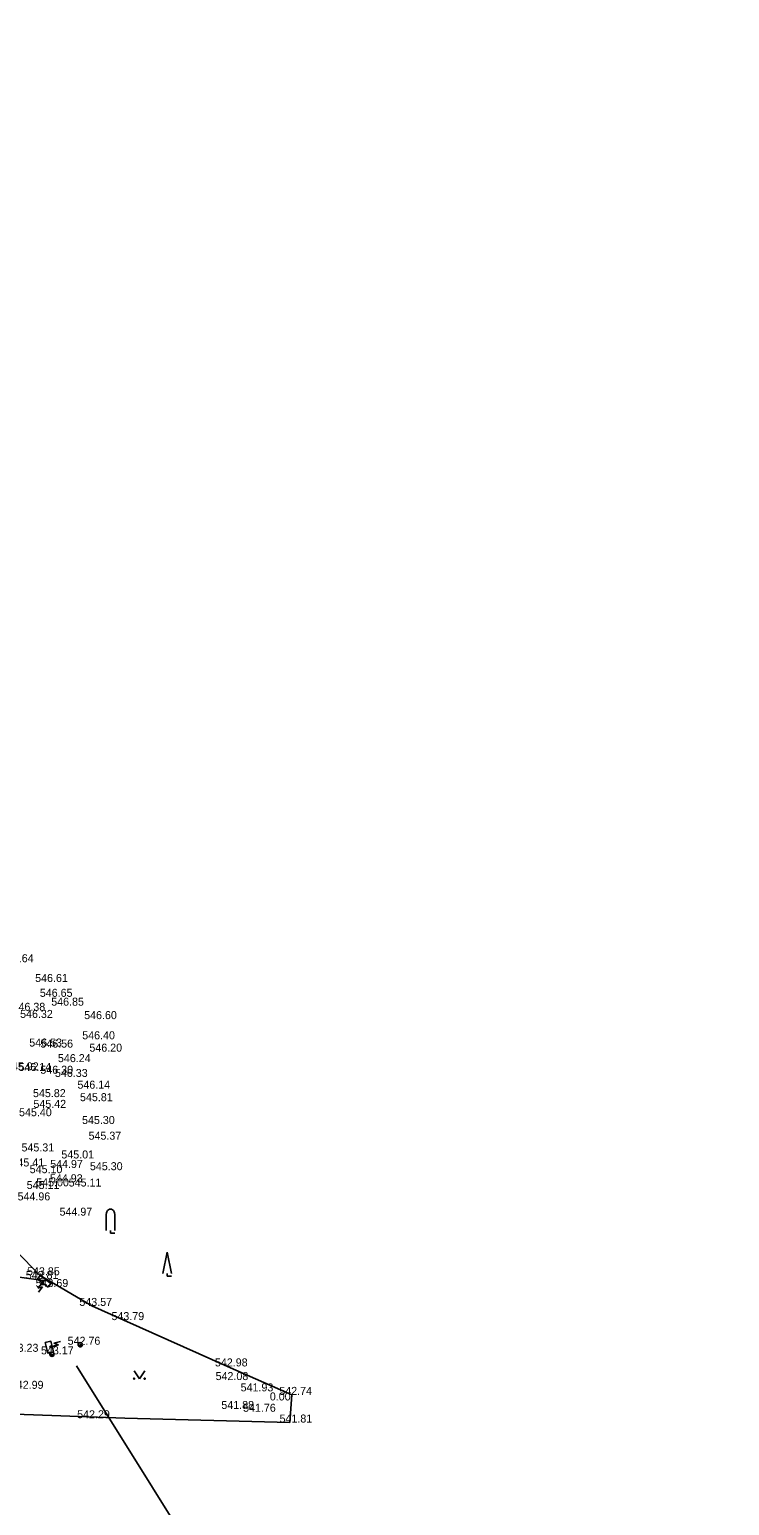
# Model space of a CAD drawing. Extents: x -669393 to -668650, y -1126925 to -1126294.
# Drawn here: x -668849.7 to -668784, y -1126670.3 to -1126531.9 of the extents above; entities that cross this region are included whole.
import ezdxf

# ---------------------------------------------------------------- set-up
doc = ezdxf.new("R2010")
doc.units = 0
for name, color, linetype in [('G_Bod_tecka', 7, 'Continuous'), ('G_Bod_vyska', 7, 'Continuous'), ('G_Ploty', 7, 'Continuous'), ('G_Ploty_vstupy', 7, 'Continuous'), ('G_Site-Rozvadece', 7, 'Continuous'), ('G_Site-Sloupy', 7, 'Continuous'), ('G_Z_ELsilove_nadz_kotovane', 7, 'Continuous'), ('G_Z_ELsilove_podz_kotovane', 7, 'Continuous'), ('G_Zelen-Znacky', 7, 'Continuous'), ('Vrstva 4', 7, 'Continuous')]:
    doc.layers.add(name, color=color, linetype=linetype)

msp = doc.modelspace()

# ---------------------------------------------------------------- linework, layer by layer
at = {"layer": 'G_Bod_tecka'}
for p, q in [((-668848.03, -1126621.19), (-668848.03, -1126621.19)), ((-668847.53, -1126622.58), (-668847.53, -1126622.58)), ((-668846.47, -1126623.41), (-668846.47, -1126623.41)), ((-668849.39, -1126624.56), (-668849.39, -1126624.56)), ((-668843.35, -1126624.67), (-668843.35, -1126624.67)), ((-668843.54, -1126626.56), (-668843.54, -1126626.56)), ((-668848.53, -1126627.24), (-668848.53, -1126627.24)), ((-668847.48, -1126627.34), (-668847.48, -1126627.34)), ((-668842.87, -1126627.72), (-668842.87, -1126627.72)), ((-668849.68, -1126629.53), (-668849.68, -1126629.53)), ((-668845.84, -1126628.7), (-668845.84, -1126628.7)), ((-668847.47, -1126629.79), (-668847.47, -1126629.79)), ((-668846.12, -1126630.09), (-668846.12, -1126630.09)), ((-668848.2, -1126631.98), (-668848.2, -1126631.98)), ((-668844.15, -1126631.19), (-668844.15, -1126631.19)), ((-668848.16, -1126632.99), (-668848.16, -1126632.99)), ((-668843.85, -1126632.36), (-668843.85, -1126632.36)), ((-668849.48, -1126633.77), (-668849.48, -1126633.77)), ((-668843.57, -1126634.5), (-668843.57, -1126634.5)), ((-668842.99, -1126635.97), (-668842.99, -1126635.97)), ((-668849.34, -1126637.07), (-668849.34, -1126637.07)), ((-668845.58, -1126637.73), (-668845.58, -1126637.73)), ((-668848.63, -1126639.11), (-668848.63, -1126639.11)), ((-668846.58, -1126638.62), (-668846.58, -1126638.62)), ((-668842.83, -1126638.83), (-668842.83, -1126638.83)), ((-668848.99, -1126640.59), (-668848.99, -1126640.59)), ((-668847.85, -1126640.34), (-668847.85, -1126640.34)), ((-668846.6, -1126639.96), (-668846.6, -1126639.96)), ((-668845.05, -1126640.36), (-668845.05, -1126640.36)), ((-668849.63, -1126641.66), (-668849.63, -1126641.66)), ((-668845.7, -1126643.09), (-668845.7, -1126643.09)), ((-668848.76, -1126648.68), (-668848.76, -1126648.68)), ((-668848.94, -1126649.03), (-668848.94, -1126649.03)), ((-668847.94, -1126649.78), (-668847.94, -1126649.78)), ((-668843.85, -1126651.55), (-668843.85, -1126651.55)), ((-668840.83, -1126652.88), (-668840.83, -1126652.88)), ((-668844.93, -1126655.19), (-668844.93, -1126655.19)), ((-668847.59, -1126656.09), (-668847.59, -1126656.09)), ((-668831.12, -1126657.22), (-668831.12, -1126657.22)), ((-668831.04, -1126658.5), (-668831.04, -1126658.5)), ((-668828.86, -1126659.56), (-668828.86, -1126659.56)), ((-668825.09, -1126659.89), (-668825.09, -1126659.89)), ((-668830.67, -1126661.21), (-668830.67, -1126661.21)), ((-668826.36, -1126660.41), (-668826.36, -1126660.41)), ((-668844.05, -1126662.08), (-668844.05, -1126662.08)), ((-668828.61, -1126661.47), (-668828.61, -1126661.47)), ((-668825.27, -1126662.48), (-668825.27, -1126662.48))]:
    msp.add_line(p, q, dxfattribs=at)
at = {"layer": 'G_Ploty'}
for p, q in [((-668849.45, -1126647.96), (-668855.46, -1126641.72)), ((-668843.85, -1126651.55), (-668840.83, -1126652.88)), ((-668831.12, -1126657.22), (-668840.83, -1126652.88)), ((-668825.09, -1126659.89), (-668831.12, -1126657.22)), ((-668825.27, -1126662.48), (-668825.09, -1126659.89)), ((-668840.75, -1126662.06), (-668856.29, -1126661.51)), ((-668825.27, -1126662.48), (-668840.75, -1126662.06))]:
    msp.add_line(p, q, dxfattribs=at)
msp.add_lwpolyline([(-668843.85, -1126651.55), (-668848.7, -1126648.71), (-668848.76, -1126648.68)], dxfattribs=at)
at = {"layer": 'G_Ploty_vstupy'}
msp.add_line((-668848.76, -1126648.68), (-668849.45, -1126647.96), dxfattribs=at)
at = {"layer": 'G_Site-Rozvadece'}
for p, q in [((-668848.94, -1126649.03), (-668848.7, -1126648.71)), ((-668848.7, -1126648.71), (-668847.7, -1126649.46)), ((-668848.94, -1126649.03), (-668847.94, -1126649.78)), ((-668848.9, -1126649.9), (-668848.35, -1126649.22)), ((-668848.47, -1126649.77), (-668848.9, -1126649.9)), ((-668848.86, -1126650.25), (-668848.47, -1126649.77)), ((-668848.35, -1126649.22), (-668848.59, -1126649.34)), ((-668848.42, -1126649.48), (-668848.35, -1126649.22)), ((-668847.7, -1126649.46), (-668847.94, -1126649.78)), ((-668846.97, -1126655.2), (-668847.82, -1126655.42)), ((-668847.61, -1126655.25), (-668847.82, -1126655.42)), ((-668847.82, -1126655.42), (-668847.56, -1126655.47)), ((-668846.79, -1126654.9), (-668847.4, -1126655.05)), ((-668847.4, -1126655.05), (-668846.97, -1126655.2))]:
    msp.add_line(p, q, dxfattribs=at)
msp.add_lwpolyline([(-668848.21, -1126654.99), (-668847.96, -1126655.98), (-668847.43, -1126655.84), (-668847.68, -1126654.86)], close=True, dxfattribs=at)
at = {"layer": 'G_Site-Sloupy'}
for centre in [(-668844.93, -1126655.19), (-668847.59, -1126656.09)]:
    msp.add_circle(centre, 0.2, dxfattribs=at)
for centre, radius in [((-668844.93, -1126655.19), 0.18), ((-668844.93, -1126655.19), 0.16), ((-668844.93, -1126655.19), 0.14), ((-668844.93, -1126655.19), 0.12), ((-668844.93, -1126655.19), 0.1), ((-668844.93, -1126655.19), 0.08), ((-668844.93, -1126655.19), 0.06), ((-668844.93, -1126655.19), 0.04), ((-668844.93, -1126655.19), 0.02), ((-668847.59, -1126656.09), 0.18), ((-668847.59, -1126656.09), 0.16), ((-668847.59, -1126656.09), 0.14), ((-668847.59, -1126656.09), 0.12), ((-668847.59, -1126656.09), 0.1), ((-668847.59, -1126656.09), 0.08), ((-668847.59, -1126656.09), 0.06), ((-668847.59, -1126656.09), 0.04), ((-668847.59, -1126656.09), 0.02)]:
    msp.add_arc(centre, radius, 180, 0, dxfattribs=at)
at = {"layer": 'G_Z_ELsilove_nadz_kotovane'}
msp.add_lwpolyline([(-668784.01, -1126754.51), (-668809.93, -1126713.68), (-668845.29, -1126657.16)], dxfattribs=at)
at = {"layer": 'G_Z_ELsilove_podz_kotovane'}
msp.add_lwpolyline([(-668862.99, -1126507.05), (-668868.36, -1126534.57), (-668870.31, -1126540.36), (-668871.27, -1126544.92), (-668872.24, -1126549.47), (-668872.88, -1126555.9), (-668873.53, -1126562.33), (-668872.56, -1126565.38), (-668872.66, -1126574.45), (-668872.93, -1126584.84), (-668873.2, -1126595.23), (-668868.61, -1126610.5), (-668866.81, -1126618.14), (-668864.25, -1126627.97), (-668861.68, -1126637.8), (-668858.49, -1126641.92), (-668855.29, -1126646.04), (-668854.01, -1126647.3), (-668852.73, -1126648.57), (-668848.15, -1126649.21)], dxfattribs=at)
msp.add_lwpolyline([(-668862.99, -1126507.05), (-668868.36, -1126534.57), (-668870.31, -1126540.36), (-668871.27, -1126544.92), (-668872.24, -1126549.47), (-668872.88, -1126555.9), (-668873.53, -1126562.33), (-668872.56, -1126565.38), (-668872.66, -1126574.45), (-668872.93, -1126584.84), (-668873.2, -1126595.23), (-668868.61, -1126610.5), (-668866.81, -1126618.14), (-668864.25, -1126627.97), (-668861.68, -1126637.8), (-668858.49, -1126641.92), (-668855.29, -1126646.04), (-668854.01, -1126647.3), (-668852.73, -1126648.57), (-668848.15, -1126649.21)], dxfattribs=at)
at = {"layer": 'G_Zelen-Znacky'}
for p, q in [((-668842.49, -1126644.47), (-668842.49, -1126642.97)), ((-668841.69, -1126642.97), (-668841.69, -1126644.47)), ((-668842.09, -1126644.47), (-668842.09, -1126644.72)), ((-668842.09, -1126644.72), (-668841.69, -1126644.72)), ((-668837.17, -1126648.5), (-668836.77, -1126646.5)), ((-668836.77, -1126646.5), (-668836.37, -1126648.5)), ((-668836.77, -1126648.5), (-668836.77, -1126648.75)), ((-668836.77, -1126648.75), (-668836.37, -1126648.75)), ((-668839.88, -1126657.62), (-668839.38, -1126658.37)), ((-668839.38, -1126658.37), (-668838.88, -1126657.62))]:
    msp.add_line(p, q, dxfattribs=at)
for centre in [(-668839.88, -1126658.37), (-668838.88, -1126658.37)]:
    msp.add_circle(centre, 0.05, dxfattribs=at)
msp.add_ellipse((-668842.09, -1126642.97), major_axis=(0, 0.5), ratio=0.8, start_param=4.712389, end_param=7.853982, dxfattribs=at)
at = {"layer": 'Vrstva 4'}
msp.add_lwpolyline([(-668862.99, -1126507.05), (-668868.36, -1126534.57), (-668870.31, -1126540.36), (-668871.27, -1126544.92), (-668872.24, -1126549.47), (-668872.88, -1126555.9), (-668873.53, -1126562.33), (-668872.56, -1126565.38), (-668872.66, -1126574.45), (-668872.93, -1126584.84), (-668873.2, -1126595.23), (-668868.61, -1126610.5), (-668866.81, -1126618.14), (-668864.25, -1126627.97), (-668861.68, -1126637.8), (-668858.49, -1126641.92), (-668855.29, -1126646.04), (-668854.01, -1126647.3), (-668852.73, -1126648.57), (-668848.15, -1126649.21)], dxfattribs=at)

# ---------------------------------------------------------------- texts
at = {"layer": 'G_Bod_vyska'}
for s, p in [('546.64', (-668852.37, -1126619.34)), ('546.61', (-668849.16, -1126621.19)), ('546.65', (-668848.72, -1126622.58)), ('546.85', (-668847.65, -1126623.41)), ('546.38', (-668851.28, -1126623.89)), ('546.32', (-668850.57, -1126624.56)), ('546.60', (-668844.56, -1126624.67)), ('546.53', (-668849.71, -1126627.24)), ('546.56', (-668848.67, -1126627.34)), ('546.40', (-668844.74, -1126626.56)), ('546.24', (-668847.02, -1126628.7)), ('546.20', (-668844.07, -1126627.72)), ('545.92', (-668851.9, -1126629.47)), ('546.14', (-668850.72, -1126629.53)), ('546.30', (-668848.67, -1126629.79)), ('546.33', (-668847.3, -1126630.09)), ('546.14', (-668845.19, -1126631.19)), ('545.82', (-668849.36, -1126631.98)), ('545.42', (-668849.32, -1126632.99)), ('545.81', (-668844.95, -1126632.36)), ('545.40', (-668850.67, -1126633.77)), ('545.30', (-668844.76, -1126634.5)), ('545.31', (-668850.44, -1126637.07)), ('545.37', (-668844.15, -1126635.97)), ('545.41', (-668851.38, -1126638.48)), ('544.97', (-668847.75, -1126638.62)), ('545.01', (-668846.7, -1126637.73)), ('545.10', (-668849.67, -1126639.11)), ('544.93', (-668847.77, -1126639.96)), ('545.30', (-668844.02, -1126638.83)), ('545.11', (-668849.95, -1126640.59)), ('545.00', (-668849.06, -1126640.34)), ('545.11', (-668846.01, -1126640.36)), ('544.96', (-668850.81, -1126641.66)), ('544.97', (-668846.87, -1126643.09)), ('543.81', (-668850.04, -1126649.03)), ('543.85', (-668849.92, -1126648.68)), ('543.69', (-668849.12, -1126649.78)), ('543.57', (-668845.01, -1126651.55)), ('543.79', (-668842, -1126652.88)), ('542.76', (-668846.11, -1126655.19)), ('543.23', (-668851.92, -1126655.85)), ('543.17', (-668848.61, -1126656.09)), ('542.98', (-668832.29, -1126657.22)), ('542.99', (-668851.44, -1126659.32)), ('542.08', (-668832.23, -1126658.5)), ('541.93', (-668829.88, -1126659.56)), ('0.00', (-668827.14, -1126660.41)), ('542.74', (-668826.25, -1126659.89)), ('542.29', (-668845.22, -1126662.08)), ('541.88', (-668831.69, -1126661.21)), ('541.76', (-668829.65, -1126661.47)), ('541.81', (-668826.23, -1126662.48))]:
    msp.add_text(s, height=0.75, dxfattribs=at).set_placement(p)

doc.saveas('drawing.dxf')
